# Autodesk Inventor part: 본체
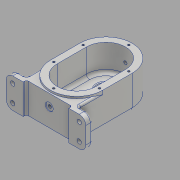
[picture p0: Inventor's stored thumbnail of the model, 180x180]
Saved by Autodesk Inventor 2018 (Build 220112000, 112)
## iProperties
Created: 2021-05
Part Number: 본체
Material: 알루미늄 6061
Document SubType Name: Modeling
Designer: admin
Density: 2.7 g/cm^3
Appearance: 알루미늄 - 평지
Mass: 752.793 g
Surface Area: 587.908 cm^2
Volume: 278.812 cm^3
Author: admin
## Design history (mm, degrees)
sketch "스케치1"
  geometry: L1 (0, -14.8)-(0, 88.8) reference; L2 (-85.4, 0)-(85.4, 0) reference; L3 (-61, 0)-(-61, 10); L4 (-61, 10)-(-40, 10); L5 (-40, 10)-(-40, 74); L6 (-40, 74)-(0, 74); L7 (-61, 0)-(-35, 0); L8 (-35, 0)-(-35, 5); L9 (-35, 5)-(0, 5); L10 (35, 5)-(0, 5); L11 (35, 0)-(35, 5); L12 (61, 0)-(35, 0); L13 (61, 0)-(61, 10); L14 (61, 10)-(40, 10); L15 (40, 10)-(40, 74); L16 (40, 74)-(0, 74); 1 further point
  constraints: 28 end point, 6 symmetric about line, 4 perpendicular, 4 point on line, 2 vertical
  dimensions: "d3" = 61 distance of point (0, 0) L3.start; "d4" = 10 distance of L3.start L3.end; "d5" = 35 distance from line of L9.end L8; "d6" = 5 distance of L7.end L8.end; "d7" = 40 distance between parallel lines of L1 L5; "d8" = 74 distance between parallel lines of L6 L2
extrude "돌출1" new body sketch "스케치1" stored distance "d9" = 46; taper "d10" = 0 deg
node "작업 평면1"
sketch "스케치2"
  geometry: L1 (-61, 10)-(-61, 0) reference; L2 (-61, 0)-(-35, 0) reference; L3 (-35, 0)-(-35, 5) reference; L4 (-35, 5)-(35, 5) reference; L5 (35, 5)-(35, 0) reference; L6 (35, 0)-(61, 0) reference; L7 (61, 0)-(61, 10) reference; L8 (61, 10)-(40, 10) reference; L9 (40, 10)-(40, 74) reference; L10 (40, 74)-(-40, 74) reference; L11 (-40, 74)-(-40, 10) reference; L12 (-40, 10)-(-61, 10) reference; L13 (-40, 92)-(40, 92); L14 (40, 92)-(40, 47); L15 (40, 47)-(-40, 47); L16 (-40, 47)-(-40, 92); C1 r 40 at (0, 47); 2 further points
  constraints: 8 end point, 2 midpoint, 2 parallel, 2 tangent, 1 centre point, 1 horizontal, 1 horizontal alignment, 1 perpendicular, 2 other
  dimensions: "d12" = 47 distance from line of C1.centre L6; "d13" = 80 diameter of C1; "d14" = 80 distance of L13.start L13.end; "d15" = 45 distance of L13.end L14.end
extrude "돌출2" join sketch "스케치2" distance "d16" = 49; taper "d17" = 0 deg
sketch "스케치3"
  geometry: L1 (0, -26.4)-(0, 158.4) reference; L2 (85.4, 0)-(-85.4, 0) reference; L3 (26, 47)-(26, 92); L4 (-26, 92)-(-26, 47); A1 r 26 centre (0, 47) between (26, 47) and (-26, 47); A2 r 26 centre (0, 92) between (26, 92) and (-26, 92); 1 further point
  constraints: 4 end point, 4 point on circle, 2 centre point, 2 point on line, 2 tangent, 2 vertical
  dimensions: "d18" = 52 diameter of A1; "d19" = 47 distance from line of A1.centre L2; "d20" = 52 diameter of A2; "d21" = 45 distance of A2.centre A1.centre
extrude "돌출3" join sketch "스케치3" distance "d22" = 11; taper "d23" = 0 deg
sketch "스케치4"
  geometry: L1 (-26, 92)-(-26, 47) reference; L2 (26, 47)-(26, 92) reference; L3 (26, 92)-(26, 47) reference; L4 (26, 92)-(26, 62); L5 (26, 62)-(-26, 62); L6 (-26, 62)-(-26, 92); A1 r 26 centre (0, 92) between (26, 92) and (-26, 92) reference; A2 r 26 centre (0, 47) between (-26, 47) and (26, 47) reference; A3 r 26 centre (0, 92) between (26, 92) and (-26, 92) reference; A4 r 26 centre (0, 92) between (26, 92) and (-26, 92); 1 further point
  constraints: 6 end point, 3 point on circle, 1 centre point, 1 coincident, 1 parallel, 1 point on line
  dimensions: "d24" = 30 distance from line of L5 A1.centre; "d25" = 52 distance of L4.end L5.end; "d26" = 30 distance of L5.end L1.start
extrude "돌출4" cut sketch "스케치4" distance "d27" = 3; taper "d28" = 0 deg
sketch "스케치5"
  geometry: L1 (0, -26.4)-(0, 158.4) reference; L2 (85.4, 0)-(-85.4, 0) reference; 2 further points
  constraints: 1 point on line, 1 other
  dimensions: "d29" = 12 distance from line of point (0, 12) L2
feature "엠보싱1" sketch "스케치5" dims "d30" = 0.5, "d31" = 0
sketch "스케치6"
  geometry: L1 (-40, 47)-(-40, 92) reference; L2 (40, 92)-(40, 47) reference; L3 (30, 92)-(30, 47); L4 (-30, 92)-(-30, 47); A1 r 40 centre (0, 92) between (40, 92) and (-40, 92) reference; A2 r 40 centre (0, 47) between (-40, 47) and (40, 47) reference; A3 r 30 centre (0, 92) between (-30, 92) and (30, 92); A4 r 30 centre (0, 47) between (-30, 47) and (30, 47); 1 further point
  constraints: 4 end point, 4 point on circle, 2 centre point, 2 coincident, 2 tangent, 2 vertical
  dimensions: "d32" = 60 diameter of A3; "d33" = 60 diameter of A4
extrude "돌출5" cut sketch "스케치6" distance "d35" = 41; taper "d36" = 0 deg
sketch "스케치7"
  geometry: L1 (30, 92)-(30, 47) reference; L2 (-30, 47)-(-30, 92) reference; C1 r 14 at (0, 92); C2 r 14 at (0, 47); A1 r 30 centre (0, 92) between (30, 92) and (-30, 92) reference; A2 r 30 centre (0, 47) between (-30, 47) and (30, 47) reference; 1 further point
  constraints: 2 centre point, 2 coincident
  dimensions: "d37" = 28 diameter of C1; "d38" = 28 diameter of C2
extrude "돌출6" cut sketch "스케치7" distance "d39" = 8; taper "d40" = 0 deg
sketch "스케치8"
  geometry: C1 r 14 at (0, 0) reference; C2 r 14 at (0, -45) reference; C3 r 11 at (0, 0); 1 further point
  constraints: 1 centre point, 1 coincident
  dimensions: "d41" = 22 diameter of C3
extrude "돌출7" cut sketch "스케치8" stored distance "d42" = 8; taper "d43" = 0 deg
sketch "스케치9"
  geometry: C1 r 11 at (0, 92) reference; C2 r 14 at (0, 92); 1 further point
  constraints: 1 centre point, 1 coincident
  dimensions: "d44" = 28 diameter of C2
extrude "돌출8" cut sketch "스케치9" distance "d45" = 4; taper "d46" = 0 deg
sketch "스케치10"
  geometry: C1 r 14 at (0, 0) reference; C2 r 10 at (0, 0); 1 further point
  constraints: 1 centre point, 1 coincident
  dimensions: "d47" = 20 diameter of C2
extrude "돌출9" cut sketch "스케치10" distance "d48" = 4; taper "d49" = 0 deg
node "작업 평면2"
sketch "스케치11"
  geometry: L1 (-40, 26)-(40, 26) reference; L2 (0, -46)-(0, 38) reference; C1 r 6 at (0, 5); 1 further point
  constraints: 1 centre point, 1 point on line
  dimensions: "d51" = 12 diameter of C1; "d52" = 21 distance from line of C1.centre L1
extrude "돌출10" join sketch "스케치11" distance "d53" = 4; taper "d54" = 0 deg
sketch "스케치12"
  geometry: C1 r 6 at (0, 0) reference; C2 r 2.293 at (0, 0); 1 further point
  constraints: 1 centre point, 1 coincident
hole "구멍1" sketch "스케치12" at (0, 0) diameter "d55" = 4.917; stored, may be unused: countersink angle "d59" = 90 deg, drill point angle "d61" = 118 deg; dims "d56" = 138, "d57" = 4, "d58" = 2, "d60" = 140
sketch "스케치13"
  geometry: C1 r 2.458 at (35, -18) reference; C2 r 6 at (35, -18); 1 further point
  constraints: 1 centre point, 1 coincident
  dimensions: "d62" = 12 diameter of C2
extrude "돌출11" cut sketch "스케치13" distance "d63" = 1; taper "d64" = 0 deg
fillet "모깎기1" dims "d65" = 10
sketch "스케치15" dims "d66" = 40
  geometry: L1 (-26, 62)-(-26, 92) reference; L2 (26, 62)-(-26, 62) reference; L3 (26, 92)-(26, 62) reference; C1 r 14 at (0, 92) reference; C2 r 3.851 at (0, 112); A1 r 26 centre (0, 92) between (26, 92) and (-26, 92) reference; 2 further points
  constraints: 1 centre point, 1 coincident, 1 vertical alignment, 2 other
hole "구멍2" sketch "스케치15" at (0, 112) diameter "d67" = 3.242; stored, may be unused: countersink angle "d71" = 90 deg, drill point angle "d73" = 118 deg; dims "d68" = 8, "d69" = 4, "d70" = 2, "d72" = 10
sketch "스케치16"
  geometry: L1 (-21, 10)-(-21, 36) reference; L2 (0, 0)-(-11, 0) reference; L3 (0, 0)-(0, 46) reference; L4 (-11, 46)-(0, 46) reference; L5 (80, 46)-(91, 46) reference; L6 (80, 0)-(80, 46) reference; L7 (91, 0)-(80, 0) reference; L8 (101, 10)-(101, 36) reference; C1 r 5.5 at (-11, 36); A1 r 10 centre (-11, 36) between (-11, 46) and (-21, 36) reference; A2 r 10 centre (-11, 10) between (-21, 10) and (-11, 0) reference; A3 r 10 centre (91, 36) between (101, 36) and (91, 46) reference; A4 r 10 centre (91, 10) between (91, 0) and (101, 10) reference; 1 further point
  constraints: 1 centre point, 1 coincident
  dimensions: "d77" = 11 diameter of C1
extrude "돌출12" cut sketch "스케치16" distance "d78" = 2; taper "d79" = 0 deg
sketch "스케치17"
  geometry: L1 (-10, -26)-(-10, 0) reference; L2 (11, -36)-(0, -36) reference; L3 (11, -36)-(11, 10) reference; L4 (0, 10)-(11, 10) reference; C1 r 5.5 at (0, 0) reference; C2 r 3.3 at (0, 0); A1 r 10 centre (0, 0) between (0, 10) and (-10, 0) reference; A2 r 10 centre (0, -26) between (-10, -26) and (0, -36) reference; 1 further point
  constraints: 1 centre point, 1 coincident
  dimensions: "d80" = 6.6 diameter of C2
extrude "돌출13" cut sketch "스케치17" stored distance "d81" = 2; taper "d82" = 0 deg
sketch "스케치18"
  geometry: L1 (30, 92)-(30, 47) reference; L2 (-30, 47)-(-30, 92) reference; L3 (-40, 47)-(-40, 92) reference; L4 (40, 92)-(40, 47) reference; L5 (35, 92)-(35, 47); L6 (-35, 92)-(-35, 47); L7 (0, -27)-(0, 162) reference; L8 (0.027, 9.908)-(0.027, 13.577) reference; L9 (-35, 47)-(35, 47); L10 (-35, 92)-(35, 92); C1 r 3.66 at (0, 127); C2 r 3.899 at (0.027, 11.742); C3 r 3.659 at (35, 92); C4 r 3.592 at (35, 47); C5 r 3.193 at (-35, 92); C6 r 2.901 at (-35, 47); A1 r 30 centre (0, 92) between (30, 92) and (-30, 92) reference; A2 r 30 centre (0, 47) between (-30, 47) and (30, 47) reference; A3 r 40 centre (0, 92) between (40, 92) and (-40, 92) reference; A4 r 40 centre (0, 47) between (-40, 47) and (40, 47) reference; A5 r 35 centre (0, 92) between (35, 92) and (-35, 92); A6 r 35 centre (0, 47) between (35, 47) and (-35, 47); 1 further point
  constraints: 8 centre point, 8 end point, 6 coincident, 5 point on circle, 2 horizontal, 2 tangent, 2 vertical, 1 midpoint, 1 point on line
  dimensions: "d83" = 70 diameter of A5; "d84" = 70 diameter of A6
hole "구멍3" sketch "스케치18" at (0, 127), (0.027, 11.742), (35, 47), (35, 92), (-35, 92), (-35, 47) diameter "d86" = 3.242; stored, may be unused: countersink angle "d90" = 90 deg, drill point angle "d92" = 118 deg; dims "d87" = 8, "d88" = 4, "d89" = 2, "d91" = 10
fillet "모깎기2" dims "d93" = 0.3
chamfer "모따기1" distance "d94" = 1; stored, may be unused: second distance "d95" = 2, angle "d96" = 45 deg
chamfer "모따기2" distance "d97" = 1; stored, may be unused: second distance "d98" = 2, angle "d99" = 45 deg
fillet "모깎기3" dims "d100" = 3
fillet "모깎기4" dims "d101" = 3
fillet "모깎기5" dims "d102" = 3
fillet "모깎기6" dims "d103" = 3
fillet "모깎기7" dims "d104" = 3
fillet "모깎기8" dims "d105" = 5
node "솔리드1"
pattern_circular "원형 패턴1" dims angle "d75" = 360 deg
mirror "미러1"
mirror "미러2"
node "투영된 루프1"
node "투영된 루프2"
node "투영된 루프3"
node "투영된 루프4"
node "투영된 루프5"
node "투영된 루프6"
node "투영된 루프7"
node "투영된 루프8"
node "투영된 루프9"
node "투영된 루프10"
node "투영된 루프11"
node "투영된 루프12"
node "투영된 루프13"
other parameters: "d11" = 26, "d50" = 135
